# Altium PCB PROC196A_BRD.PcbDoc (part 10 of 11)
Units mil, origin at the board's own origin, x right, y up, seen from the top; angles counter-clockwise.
Board outline 3346.45 x 4921.26 mil, 8 copper layers (Top Layer, GND1, SIG1, PWR1, PWR2, SIG2, GND2, Bottom Layer), stack 54.534 mil thick; 736 components, 498 nets, 3030 pads, 1279 vias.
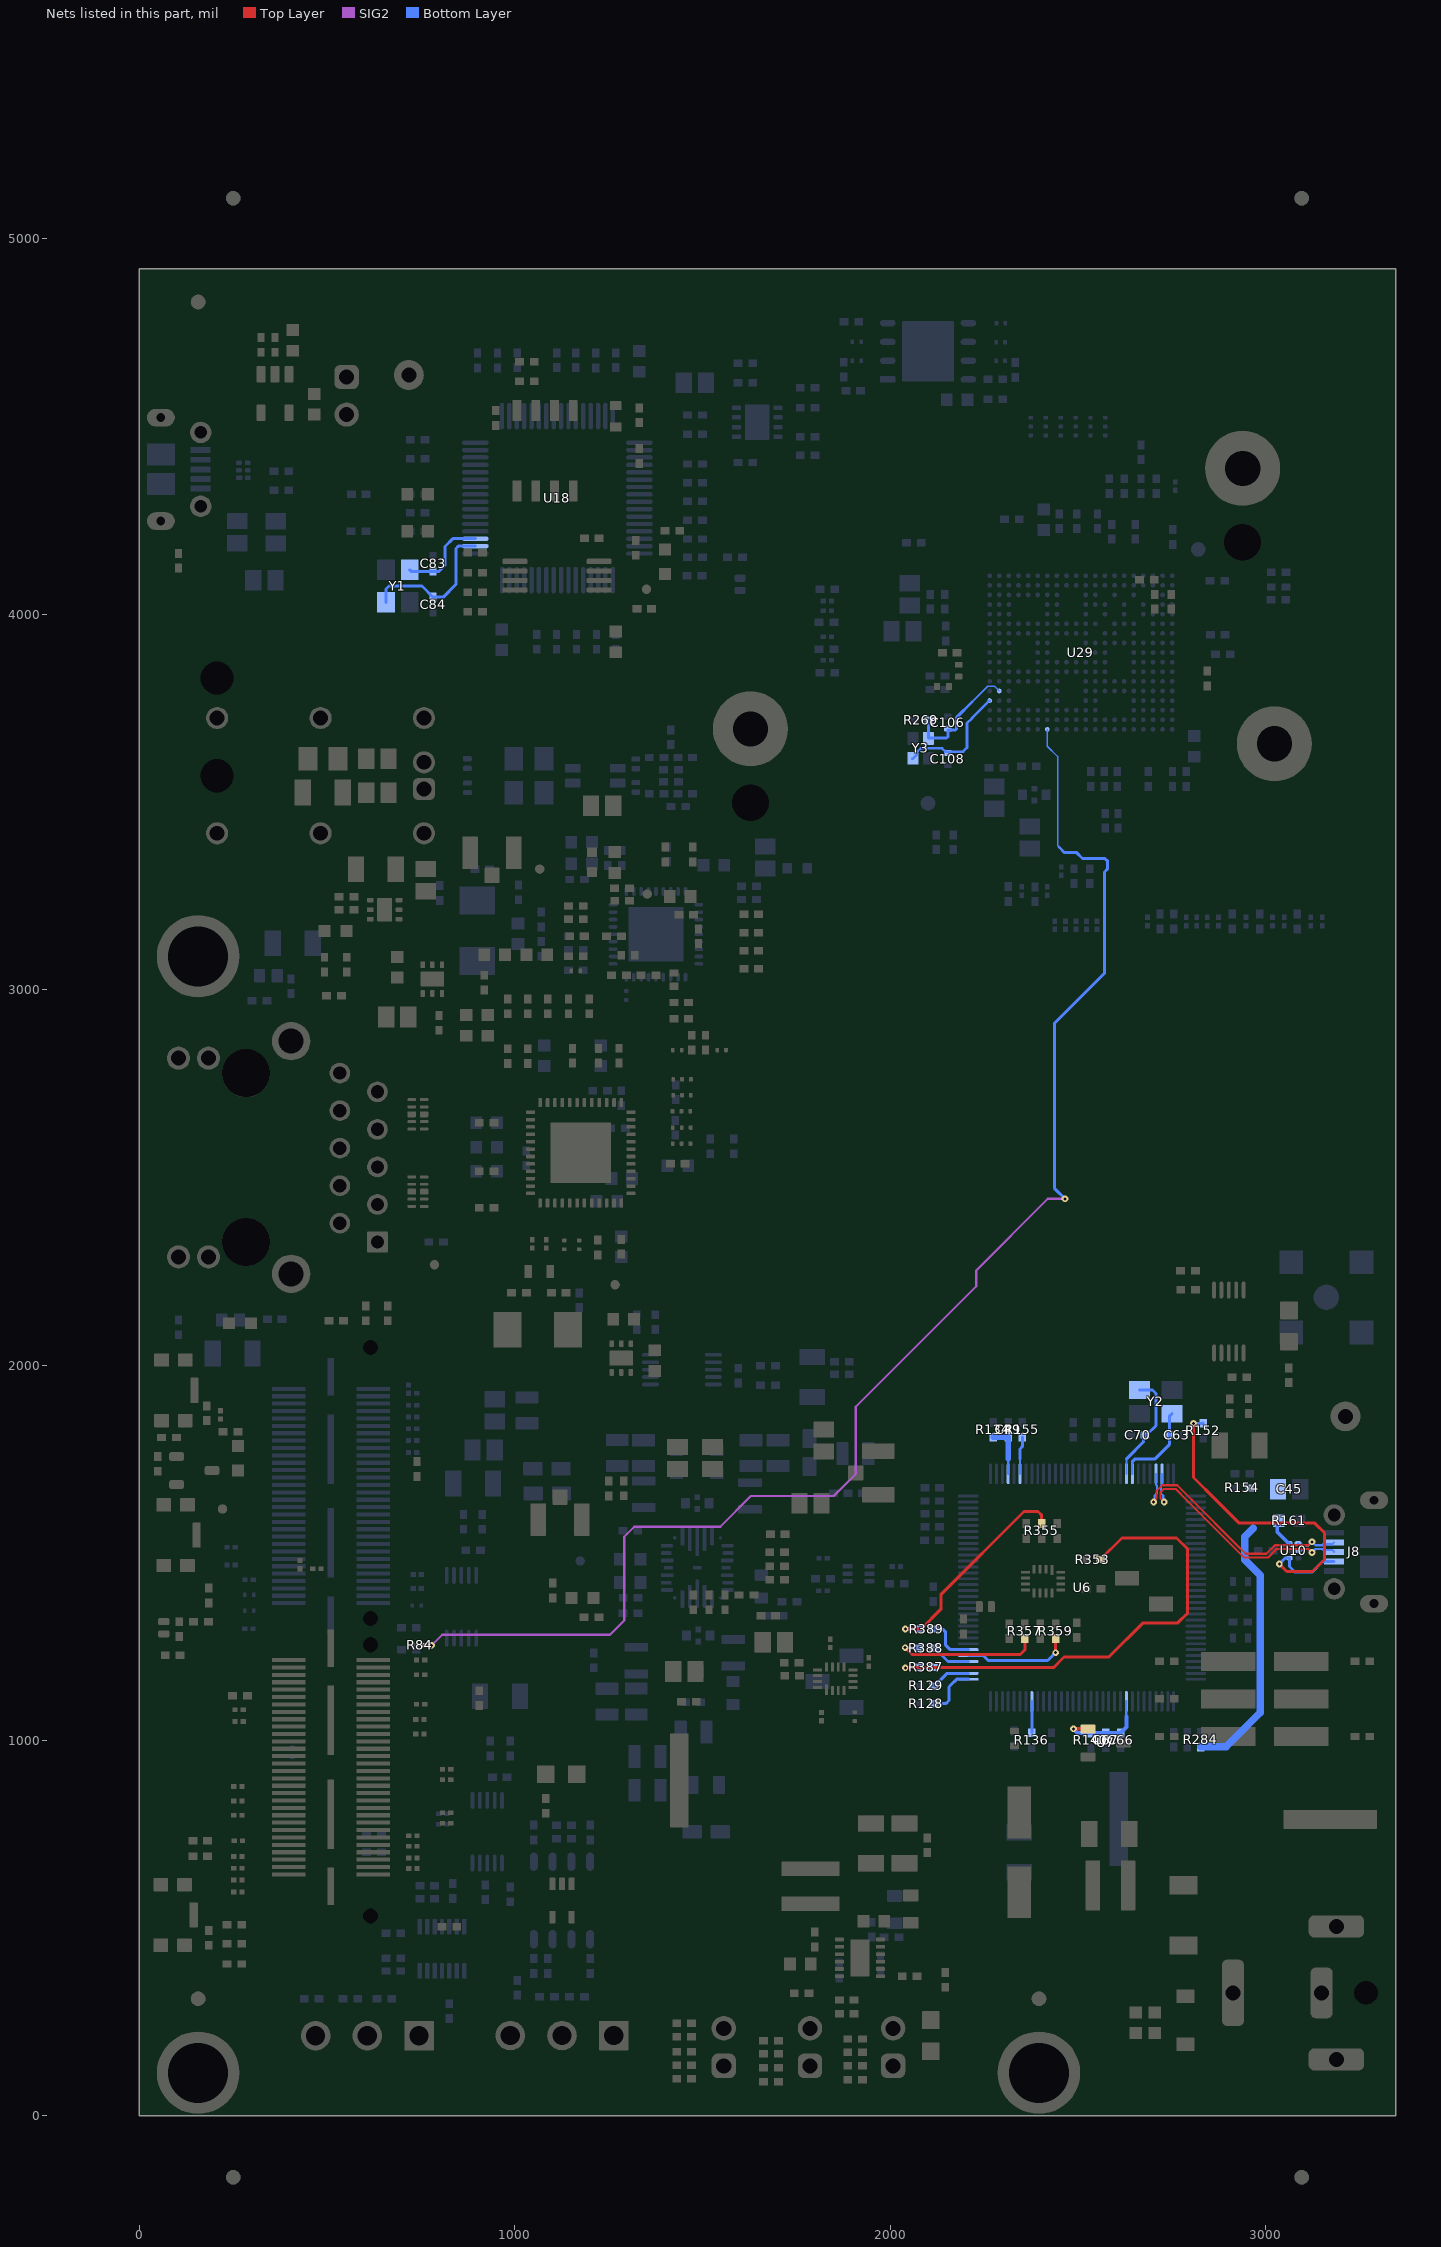
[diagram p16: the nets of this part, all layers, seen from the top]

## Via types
v1: diameter 18, hole 8, Top Layer to Bottom Layer, tented both sides, 1230 vias
v2: diameter 19.68, hole 7.87, Top Layer to Bottom Layer, 30 vias
v3: diameter 20, hole 10, Top Layer to Bottom Layer, tented both sides, 11 vias
v4: diameter 10, hole 4, SIG2 to Bottom Layer, tented both sides, 6 vias
v5: diameter 19.68, hole 7.87, Top Layer to Bottom Layer, tented both sides, 2 vias

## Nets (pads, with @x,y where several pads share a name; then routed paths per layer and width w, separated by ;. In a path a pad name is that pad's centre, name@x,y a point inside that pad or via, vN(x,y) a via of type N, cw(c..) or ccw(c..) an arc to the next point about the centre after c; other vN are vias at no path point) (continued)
XDS_TCK: R353.1 R387.1 | length 1284
  Top Layer w8: v1(2040.57,1193.5) 2040.92,1193.85 2435.24,1193.85 2463.4,1222.02 2582.67,1222.02 2674.07,1313.41 2766.68,1313.41 2792.65,1339.39 2792.65,1509.88 2763.28,1539.25 2617.53,1539.25 R353.1@2560.2,1481.93
  Bottom Layer w8: v1(2040.57,1193.5) 2041.1,1194.03 2072.24,1194.03 R387.1@2072.77,1194.56
XDS_TDI: R355.1 R389.1 | length 575.1
  Top Layer w8: v1(2040.67,1296.89) 2082.72,1296.89 2135.25,1349.42 2135.25,1388.25 2356.85,1609.86 2393.85,1609.86 2403.67,1600.04 R355.1@2403.67,1577.67
  Bottom Layer w8: v1(2040.67,1296.89) R389.1@2073.94,1296.89
XDS_TDO: R359.1 U6.37 | length 284.8
  Top Layer w8: R359.1@2440.88,1271.26 2441.05,1271.09 2441.05,1233.88 v1(2441.23,1233.71)
  Bottom Layer w8: U6.37@2208.34,1226.06 2247.87,1226.06 2261.17,1212.76 2419.8,1212.76 2440.75,1233.71 v1(2441.23,1233.71)
XDS_TMS: R357.1 R388.1 | length 395.1
  Top Layer w8: v1(2040.16,1247.13) 2058.47,1228.81 2346.5,1228.81 2358.88,1241.19 R357.1@2358.88,1271.26
  Bottom Layer w8: v1(2040.16,1247.13) 2040.66,1246.63 2072.85,1246.63 R388.1@2073.35,1246.13
XDSET_1_D_N: J8.2 U6.93 U10.1 | length 730.3
  Top Layer w5.65: v1(2702.21,1635.51) 2702.21,1637.21 2709.99,1644.99 2709.99,1665.1 2724.85,1679.96 2764.89,1679.96 2805.04,1639.81 2925.31,1519.53 2947.49,1497.36 3002.55,1497.36 3025.32,1520.13 3114.46,1520.13 3123.36,1529.03 v1(3123.95,1529.03)
  Bottom Layer w5.65: v1(2702.21,1635.51) 2704.57,1637.87 2704.57,1652.27 2711.11,1658.81 2711.11,1678.78 2708.76,1681.13 2708.76,1709.88 U6.93@2708.34,1710.31 ; U10.1@3086.64,1524.87 3089.03,1522.49 3097.09,1522.49 3099.46,1520.13 3114.46,1520.13 3123.36,1529.03 v1(3123.95,1529.03) 3124.53,1529.03 3133.43,1520.13 3151.2,1520.13 3153.85,1522.77 3178.02,1522.77 J8.2@3183.06,1527.82
XDSET_1_D_P: J8.3 U6.94 U10.2 | length 713.3
  Top Layer w5.65: v1(2730.21,1635.51) 2720.19,1645.53 2720.19,1660.87 2729.07,1669.76 2760.66,1669.76 2790.61,1639.81 2925.31,1505.11 2943.26,1487.16 3006.78,1487.16 3029.55,1509.93 3114.46,1509.93 3123.36,1501.03 v1(3123.95,1501.03)
  Bottom Layer w5.65: U6.94@2724.08,1710.31 2723.66,1709.88 2723.66,1681.13 2721.31,1678.78 2721.31,1658.81 2727.85,1652.27 2727.85,1637.87 v1(2730.21,1635.51) ; U10.2@3087.63,1505.18 3090.01,1507.56 3097.09,1507.56 3099.46,1509.93 3114.46,1509.93 3123.36,1501.03 v1(3123.95,1501.03) 3124.53,1501.03 3133.43,1509.93 3151.2,1509.93 3153.85,1507.28 3178.02,1507.28 J8.3@3183.06,1502.23
XDSET_1_ID: J8.4 R152.1 U10.4 | length 985.3
  Top Layer w8: v1(2808.45,1844.58) 2808.45,1700.36 2869,1639.81 2930,1578.81 3131.54,1578.81 3157.22,1553.13 3157.22,1481.93 3125.4,1450.11 3057.05,1450.11 v1(3036.9,1470.26)
  Bottom Layer w8: v1(2808.45,1844.58) 2808.73,1844.86 2833.61,1844.86 R152.1@2833.89,1845.13 ; v1(3036.9,1470.26) 3052.13,1485.5 U10.4@3064.01,1485.5 3064.01,1463.14 3078.75,1448.4 3123.69,1448.4 3151.93,1476.64 J8.4@3183.06,1476.64
XDSET_1_VBUS: C45.1 R154.2 R161.2 R284.2 U10.6 | length 788.4
  Bottom Layer w10: R161.2@3031.43,1585.36 3031.43,1555.48 3062.04,1524.87 U10.6@3064.01,1524.87
  Bottom Layer w20: R284.2@2828,982.63 2894.91,982.63 2986.69,1074.41 2986.69,1440.36 2945.42,1481.63 2945.42,1542.86 2967.36,1564.8
XDSET_NRST: R155.1 U6.70 | length 100
  Bottom Layer w6: U6.70@2346.13,1710.31 2346.13,1750.08
  Bottom Layer w8: 2346.13,1750.08 2346.27,1750.22 2346.27,1776.47 2352.4,1782.6 R155.1@2352.4,1807.73
XDSET_OSC0: C70.1 U6.88 Y2.1 | length 293.1
  Bottom Layer w6: U6.88@2629.6,1710.31 2629.6,1750.31
  Bottom Layer w8: 2629.6,1750.31 2629.95,1750.66 ; 2630.3,1750.31 2630.3,1750.8 2675.7,1796.2 2675.7,1810 C70.1@2679.33,1813.63 ; Y2.1@2664.34,1933.67 2699.14,1933.67 2708.25,1924.56 2708.25,1838.61 C70.1@2683.27,1813.63
XDSET_OSC1: C63.2 U6.89 Y2.3 | length 235.2
  Bottom Layer w6: U6.89@2645.34,1710.31 2645.34,1742.37
  Bottom Layer w8: 2645.34,1742.37 2653.07,1750.1 2706.08,1750.1 2743.77,1787.79 C63.2@2743.77,1813.63 2743.77,1863.49 Y2.3@2750.96,1870.68
XDSET_TCK: R387.2 U6.35 | length 92.3
  Bottom Layer w8: R387.2@2116.08,1194.56 U6.35@2208.34,1194.56
XDSET_TDI: R389.2 U6.38 | length 134.2
  Bottom Layer w7.8: 2180.78,1241.8 U6.38@2208.34,1241.8
  Bottom Layer w8: R389.2@2117.24,1296.89 2140.06,1296.89 2147.12,1289.83 2147.12,1255.17 2160.48,1241.8 2180.78,1241.8
XDSET_TMS: R388.2 U6.36 | length 101.8
  Bottom Layer w8: R388.2@2120.59,1244.16 2154.42,1210.32 U6.36@2208.34,1210.31
XDSET_UARTA_RX: R129.2 U6.34 | length 106.2
  Bottom Layer w8: R129.2@2116.08,1145.19 2118.05,1145.19 2145.52,1172.65 2151.67,1178.81 U6.34@2208.34,1178.81
XDSET_UARTA_TX: R128.2 U6.33 | length 139.8
  Bottom Layer w8: R128.2@2116.65,1097.79 2147.98,1097.79 2156.86,1106.67 2156.86,1142.59 2160.54,1146.27 2177.29,1163.03 U6.33@2184.66,1163.03 ; U6.33@2184.69,1163.06 U6.33@2208.34,1163.06
XDSET_UARTB_TX: R136.2 U6.25 | length 83.4
  Bottom Layer w8: R136.2@2377.63,1020.63 2377.63,1065.5 U6.25@2377.63,1104.01
XDSET_VBAT: C49.1 R134.1 U6.68 | length 136.9
  Bottom Layer w7: U6.68@2314.69,1710.36 2314.69,1748.26
  Bottom Layer w10: 2314.69,1748.26 2314.69,1750.65
  Bottom Layer w15: R134.1@2275.06,1807.73 C49.1@2314.64,1807.73 ; 2314.69,1750.65 C49.1@2314.69,1807.67
XDSET_VREFA: C66.2 C67.2 R140.1 U6.9 U7.1 | length 259.7
  Top Layer w10: v1(2488.42,1030.91) U7.1@2527.23,1030.91
  Bottom Layer w7: U6.9@2629.6,1104.01 2629.6,1064.04 2629.77,1063.86
  Bottom Layer w10: v1(2488.42,1030.91) 2499.28,1020.05 R140.1@2535.11,1020.05 C67.2@2574.86,1020.05 C66.2@2614.2,1020.05 2629.6,1035.45 2629.6,1064.04
XI_FTDI: C84.1 U18.2 Y1.1 | length 401.2
  Bottom Layer w8: Y1.1@657.29,4032.13 657.29,4067.56 665.17,4075.43 752.83,4075.43 C84.1@782.36,4045.91 809.61,4045.91 843.6,4079.89 843.6,4175.65 849.68,4181.73 U18.2@895.17,4181.73
XO_FTDI: C83.1 U18.3 Y1.3 | length 241.6
  Bottom Layer w8: Y1.3@720.28,4118.74 724.22,4114.8 C83.1@782.36,4114.8 798.14,4114.8 814.14,4130.81 814.14,4180.68 834.89,4201.42 U18.3@895.17,4201.42
XREF_CLK0: R84.1 U29.A7 | length 3902.6
  Top Layer w8: R84.1@758.27,1253.41 758.33,1253.36 778.61,1253.36 v1(778.66,1253.31)
  SIG2 w6: v1(778.66,1253.31) 807.16,1281.81 1253.81,1281.81 1291.44,1319.44 1291.44,1542.44 1318.5,1569.5 1547.5,1569.5 1629,1651 1849.99,1651 1908.75,1709.76 1908.75,1889.29 2229.37,2209.91 2229.37,2252.24 2420.08,2442.95 v1(2465.85,2442.95)
  Bottom Layer w4: U29.A7@2418.84,3693.52 2418.84,3648.89 2446.29,3621.44 2446.29,3383.85 2449.71,3380.43
  Bottom Layer w8: 2449.71,3380.43 2464.91,3365.24 2497.37,3365.24 2512.83,3349.78 2572.18,3349.78 2579.52,3342.44 2579.52,3322.46 2570.9,3313.84 2570.9,3043.71 2437.36,2910.17 2437.36,2471.44 v1(2465.85,2442.95)
XTALM: C108.1 U29.D1 Y3.3 | length 318.8
  Bottom Layer w7: Y3.3@2059.55,3615.18 2071.4,3627.03 2071.4,3632.67 2081.73,3643 2138.68,3643 2147.48,3634.2 2153.94,3634.2 2153.98,3634.16 2194.35,3634.16 2205,3644.81 2205,3709.99 2217.96,3722.95 2218.62,3723.61 U29.D1@2265.3,3770.29
XTALP: C106.1 R269.1 U29.E2 Y3.1 | length 325
  Bottom Layer w4: 2217.96,3766.53 2218.62,3767.19 2260.04,3808.61 2278.17,3808.61 U29.E2@2290.89,3795.89
  Bottom Layer w8: R269.1@2102.86,3718.43 2102.86,3670.3 2150.47,3670.3 2153.98,3673.82 C106.1@2153.98,3689.93 ; C106.1@2153.98,3692.03 2173.72,3692.03 2177.23,3695.54 2177.23,3725.81 2217.96,3766.53
pads on no net: D15.1S D15.2S D17.1S D17.2S D18.1S D18.2S D19.1S D19.2S FID1.1 FID2.1 FID3.1 FID4.1 FID5.1 FID6.1 FID7.1 FID8.1 FID9.1 FID10.1 FID11.1 FID12.1 FID13.1 FID14.1 FID15.1 FID16.1 J4.ALIGN1 J4.ALIGN2 J7.1 J7.2 J7.3 J7.14 J7.25 J7.31 J7.33 J7.35 J7.47 J7.MH1 J7.MH2 J8.7 J8.8 J9. J12.ALIGN J16.4 J19.10 J19.11 J19.14 J19.18 J19.20 J19.22 J19.24 J19.26 J19.28 J19.30 J19.32 J19.34 J19.35 J19.36 J19.37 J19.38 J19.39 J19.40 J19.41 J19.43 J19.45 J19.47 J19.49 J19.51 J19.53 J19.55 J19.59 J19.MH1 J19.MH2 LBL1.0 SW1.1 SW1.3 SW2.1 SW2.3 SW3.1 SW3.3 U2.11 U4.17 U4.18 U4.19 U4.20 U5.11 U6.2 U6.3 U6.4 U6.5 U6.6 U6.11 U6.12 U6.13 U6.14 U6.15 U6.18 U6.19 U6.20 U6.21 U6.22 U6.23 U6.24 U6.27 U6.29 U6.30 U6.31 U6.32 U6.41 U6.42 U6.43 U6.44 U6.45 U6.46 U6.49 U6.50 U6.53 U6.54 U6.56 U6.57 U6.65 U6.67 U6.71 U6.72 U6.73 U6.74 U6.75 U6.76 U6.77 U6.78 U6.81 U6.82 U6.83 U6.84 U6.85 U6.86 U6.91 U6.92 U6.97 U6.98 U6.99 U6.100 U6.102 U6.103 U6.104 U6.105 U6.106 U6.107 U6.108 U6.109 U6.110 U6.111 U6.112 U6.116 U6.117 U6.118 U6.119 U6.120 U6.121 U6.123 U6.124 U6.125 U6.126 U6.127 U6.128 U7.3 U9.3 U11.3 U12.3 U13.3@725.63,2668.11 U13.8@758.51,2668.11 U14.3@725.63,2462.03 U14.8@758.51,2462.03 U15.13 U15.20 U15.21 U15.22 U15.23 U15.48 U15.49@1121.99,2511.6 U15.49@1121.99,2565.54 U15.49@1121.99,2619.48 U15.49@1175.93,2511.6 U15.49@1175.93,2565.54 U15.49@1175.93,2619.48 U15.49@1229.86,2511.6 U15.49@1229.86,2565.54 U15.49@1229.86,2619.48 U16.5 U16.7@762.86,3028.35 U16.7@798.3,3028.35 U17.2 U17.5 U17.7@1266.22,2018.66 U17.7@1301.66,2018.66 U18.21 U18.22 U18.23 U18.24 U18.29 U18.30 U18.33 U18.40 U18.41 U18.43 U18.44 U18.57 U18.58 U18.59 U18.60 U19.6 U19.7 U20.7 U20.9@1645.89,4487 U20.9@1645.89,4536.61 U22.3 U27.4 U32.1 U33.7@653.41,3195.51 U33.7@653.41,3230.94

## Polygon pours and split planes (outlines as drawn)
GND on Top Layer "Top Layer-GND" (solid, remove dead copper, pour order 491): 3345.95,4921.06 3345.96,2921.78 3345.96,-0.19 -0.49,-0.19 -0.49,4921.06
3V3 on Top Layer "Top Layer-3V3" (solid, remove dead copper, pour order 306): 2899.79,1841.57 2899.79,1754.44 2912.56,1741.67 2912.56,1713.58 2817.58,1713.58 2817.58,1841.57
PMICOUT_1V8 on Top Layer "Top Layer-PMICOUT_1V8" (solid, remove dead copper, pour order 91): 1734.93,1993.84 1396.11,1993.84 1389.74,2000.93 1302.53,2000.93 1302.53,1935.81 1678.36,1935.81 1716.32,1897.86 1716.32,1821.54 1683.64,1788.86 1683.8,1674.22 1776.66,1674.22 1776.66,1952.1
1V2 on Top Layer "NONET_L-01_P-001" (solid, remove dead copper, pour order 12): 2672,4118 2676,4114 2676,4078.63 2673.4,4076.03 2659.03,4076.03 2648.69,4065.69 2648.69,4040.72 2669.61,4019.81 2763.09,4019.81 2763.09,3978 2618.85,3978 2607.15,3989.7 2607.6,3992 2607.6,4111.4 2607,4112 2613,4118
ERTH_GND on Top Layer "ERTH_GND_L01_P155" (solid, remove dead copper, pour order 155): 362.83,2133.63 482.54,2253.34 482.54,2818.61 523.85,2859.92 523.85,3099.48 374.2,3099.48 181.29,2906.57 0,2906.57 0,2214.38 144.93,2214.38 225.68,2133.63
3V3_VIO on Top Layer "Top Layer-3V3_VIO 1" (solid, pour order 15): 1657.48,1374.02 1622.05,1374.02 1622.05,1401.57 1688.98,1401.57 1712.6,1377.95 1712.6,1358.27 1755.91,1358.27 1771.65,1342.52 1771.65,1322.83 1755.91,1307.09 1681.1,1307.09 1681.1,1366.14 1677.17,1370.08
REGOUT_3V3 on Top Layer "Top Layer-REGOUT_3V3 5" (solid, pour order 35): 1589.76,1358.43 1605.03,1373.69 1618.17,1370.02 1649.61,1346.46 1669.29,1346.46 1669.29,1318.9 1589.76,1318.9
1V8_FILTERED on Top Layer "Top Layer-1V8_FILTERED" (solid, pour order 109): 1791.22,1791.63 1876.56,1791.63 1879.17,1790.09 1944.37,1724.88 1944.37,1698.73 1838.45,1592.81 1803.49,1592.81 1796.4,1599.91 1796.4,1680.45 1791.22,1685.62
AGND on Top Layer "AGND_L01_P083" (solid, pour order 83): 1547.63,1463.97 1519.54,1491.88 1503.96,1491.88 1494.48,1481.94 1477.42,1481.94 1470.52,1491.88 1453.33,1491.88 1422.63,1463.97 1422.63,1454.09 1451.77,1424.94 1464.92,1424.94 1476.93,1436.94 1493.43,1436.94 1505.42,1424.94 1519.13,1424.95 1547.63,1453.45
V3V3_PHY on Top Layer "Top Layer-V3V3_PHY" (solid, remove dead copper, pour order 473): 680.83,3248.56 693.5,3248.56 730.43,3285.5 812.08,3285.5 812.07,3189.54 741.36,3189.54 703.9,3227 680.83,3227
VBAT_INT on Top Layer "Top Layer-VBAT_INT 1" (solid, remove dead copper, pour order 461): 621.92,3230.25 621.92,3392.27 521.58,3392.27 521.58,3270.42 595.63,3270.42 595.63,3230.94
1V0_ETH2 on Top Layer "Top Layer-1V0_ETH2" (solid, pour order 444): 1533.35,3267.26 1454.57,3267.26 1452.34,3265.03 1452.34,3231.56 1464.84,3219.06 1464.84,3142.55 1533.35,3142.55
1V0_ETH2 on Top Layer "Top Layer-1V0_ETH2 1" (solid, pour order 438): 1210.04,3229.6 1210.04,3261.72 1193.24,3278.06 1193.24,3331.1 1284.77,3331.1 1284.77,3212.8 1226.84,3212.8
PVIN3V3 on Top Layer "Top Layer-REGOUT_3V3 2" (solid, pour order 434): 1451.41,1235.23 1451.41,1056 1374.21,1056 1374.21,1235.23
5V0 on Top Layer "Bottom Layer-5V0" (solid, remove dead copper, pour order 420): 1636.71,1296.64 1686.46,1296.9 1686.46,1210.31 1636.71,1210.31
VDDIO_ETH2 on Top Layer "Top Layer-VDDIO_ETH2" (solid, pour order 406): 955.19,3117.63 1053.4,3117.63 1053.4,3031.08 1053.81,3030.67 955.19,3030.67
REGOUT_3V3 on Top Layer "Top Layer-REGOUT_3V3 1" (solid, remove dead copper, pour order 404): 764.83,3172.17 634.18,3172.17 634.18,3060.82 743.4,3060.82 747.04,3057.18 764.83,3057.18
GND on Top Layer "Top Layer-GND 11" (solid, remove dead copper, pour order 402): 1531.07,983.22 1531.07,741.65 1506.21,716.79 1416.2,716.79 1406.4,726.59 1406.4,1023.56 1408.85,1026.01 1510.05,1026.01 1530.2,1005.87
NetJ10_6 on Top Layer "Top Layer-NetJ10_6" (solid, remove dead copper, pour order 362): 192.3,4450.41 199.96,4458.07 199.96,4517.55 164.33,4553.18 -19.57,4553.18 -19.57,4151.18 192.3,4151.18 192.3,4304.73 179.15,4317.88 113.86,4317.88 104.25,4327.49 104.25,4449.7
1V0_ETH on Top Layer "Top Layer-1V0_ETH" (solid, remove dead copper, pour order 348): 1296.98,2141.21 1311.38,2155.61 1386.85,2155.61 1395.36,2164.13 1395.36,2183.88 1459.39,2183.88 1459.39,2075.16 1356.85,2075.16 1329.08,2047.39 1302.53,2047.39 1302.53,2092.99 1296.98,2098.54
GND on Top Layer "Top Layer-GND 2" (solid, remove dead copper, pour order 346): 2176.78,711.94 2577.25,711.94 2577.25,932.74 2176.78,932.74
NetC149_2 on Top Layer "Top Layer-NetC144_1" (solid, remove dead copper, pour order 320): 513.96,4556.1 528.55,4570.69 590.17,4570.69 590.17,4506.02 560.91,4476.76 373.17,4476.76 373.17,4556.1
GND on Top Layer "Top Layer-GND 4" (solid, remove dead copper, pour order 312): 2528.58,0 2528.58,233.08 2804.91,233.08 2847.83,190.17 3057.35,190.17 3057.35,834.26 3346.48,834.26 3346.48,0
2V5_ETH on Top Layer "Top Layer-2V5_ETH" (solid, remove dead copper, pour order 310): 763.1,2998.19 763.1,2863.36 693.44,2863.36 693.44,2953.71 737.93,2998.19
PVIN3V3 on Top Layer "Top Layer-REGOUT_3V3 3" (solid, remove dead copper, pour order 191): 1559.41,1645.77 1573.41,1659.77 1573.59,1745.55 1395.36,1745.55 1395.36,1634.29 1406.47,1623.18 1445.2,1623.18 1467.8,1645.77
3V3_VIO on Top Layer "Top Layer-REGOUT_3V3 4" (solid, remove dead copper, pour order 296): 2961.69,1832.51 2961.69,1714.16 3052.13,1714.16 3052.13,1832.51
VDDIO_ETH on Top Layer "Top Layer-VDDIO_ETH" (solid, remove dead copper, pour order 271): 1210.1,3009.46 1210.1,2965.79 905.21,2965.79 905.21,3009.46
GND on Top Layer "Top Layer-GND 1" (solid, remove dead copper, pour order 263): 1884.61,296.8 1884.61,710.97 2144.31,710.97 2144.31,567.75 1943.12,567.75 1943.12,296.8
NetC21_2 on Top Layer "Top Layer-NetC21_2" (solid, remove dead copper, pour order 259): 1878.5,463.27 1878.5,592.57 1686.46,592.57 1686.46,470.73 1828.07,470.73 1828.07,463.27
REGOUT_3V3 on Top Layer "Top Layer-REGOUT_3V3" (solid, remove dead copper, pour order 211): 2109.97,923.35 2121.65,911.99 2121.65,732.61 1872.59,732.61 1872.59,620.13 1691.73,620.13 1691.73,815.1 1799.98,923.35
VBAT_INT on Top Layer "Top Layer-VBAT_INT" (solid, remove dead copper, pour order 203): 2577.25,377.21 2076.18,377.2 1993.39,460 1962.34,460 1962.34,542.58 2187.62,542.58 2187.62,699.15 2577.25,699.15
NetC100_1 on Top Layer "Top Layer-NetC100_1" (solid, remove dead copper, pour order 199): 2906.52,534.03 2906.52,816.38 2870.34,852.57 2626.94,852.57 2598.1,823.73 2598.1,534.03
NetC104_1 on Top Layer "Top Layer-NetC104_1" (solid, remove dead copper, pour order 193): 2640.27,505.4 2904.71,505.4 2947.34,462.78 2947.34,239.11 2841.68,239.11 2828.7,252.09 2624.02,252.09 2599.66,276.45 2599.66,464.79
GND on GND2 "GND1-GND" (solid, remove dead copper, pour order 449): 0,4921.25 3346.45,4921.25 3346.45,0 0,0
ERTH_GND on GND2 "ERTH_GND_L07_P410" (solid, remove dead copper, pour order 410): 362.83,2133.24 482.54,2252.95 482.54,2818.22 523.85,2859.53 523.85,3099.09 374.2,3099.09 181.29,2906.18 0,2906.18 0,2213.99 144.93,2213.99 225.68,2133.24
AGND on GND2 "AGND_L07_P289" (solid, pour order 289): 1547.63,1463.97 1519.54,1491.88 1503.96,1491.88 1494.48,1481.94 1477.42,1481.94 1470.52,1491.88 1453.33,1491.88 1422.63,1463.97 1422.63,1454.09 1451.77,1424.94 1464.92,1424.94 1476.93,1436.94 1493.43,1436.94 1505.42,1424.94 1519.13,1424.95 1547.63,1453.45
GND on GND1 "" (solid, remove dead copper, pour order 451): 0,4921.26 3346.45,4921.26 3346.45,0 0,0
ERTH_GND on GND1 "ERTH_GND_L02_P416" (solid, remove dead copper, pour order 416): 362.83,2133.63 482.54,2253.34 482.54,2818.61 523.85,2859.92 523.85,3099.48 374.2,3099.48 181.29,2906.57 0,2906.57 0,2214.38 144.93,2214.38 225.68,2133.63
AGND on GND1 "AGND_L02_P283" (solid, pour order 283): 1547.63,1463.97 1519.54,1491.88 1503.96,1491.88 1494.48,1481.94 1477.42,1481.94 1470.52,1491.88 1453.33,1491.88 1422.63,1463.97 1422.63,1454.09 1451.77,1424.94 1464.92,1424.94 1476.93,1436.94 1493.43,1436.94 1505.42,1424.94 1519.13,1424.95 1547.63,1453.45
GND on SIG1 "GND_L03_P459" (solid, remove dead copper, pour order 459): 0,4921.25 0,0 3346.45,0 3346.45,4921.25
FTDI_VBUS on SIG1 "SIG1-FTDI_VBUS" (solid, remove dead copper, pour order 336): 1554.4,4330.22 1623.26,4330.22 1623.26,4445.07 1555.33,4445.07
AGND on SIG1 "AGND_L03_P253" (solid, pour order 253): 1547.63,1463.97 1519.54,1491.88 1503.96,1491.88 1494.48,1481.94 1477.42,1481.94 1470.52,1491.88 1453.33,1491.88 1422.63,1463.97 1422.63,1454.09 1451.77,1424.94 1464.92,1424.94 1476.93,1436.94 1493.43,1436.94 1505.42,1424.94 1519.13,1424.95 1547.63,1453.45
FTDI_VBUS on SIG1 "SIG1-FTDI_VBUS 1" (solid, remove dead copper, pour order 255): 343.71,4161.9 343.71,4086.01 457.04,4086.01 457.04,4161.9
GND on Bottom Layer "Bottom Layer-GND 7" (solid, remove dead copper, pour order 492): 0,4921.26 3346.45,4921.26 3346.45,0.01 0,0.01
1V2 on Bottom Layer "NONET_L-01_P-001" (solid, remove dead copper, pour order 121): 2561.95,4051.79 2561.95,3977.86 2575.61,3964.2 2699.97,3964.2 2710.78,3975.02 2710.78,4033.15 2679.12,4064.81 2574.97,4064.81
GND on Bottom Layer "NONET_L-01_P-001" (solid, remove dead copper, pour order 493): 2118.44,3789.97 2078.84,3789.97 2071,3797.81 2071,3842.81 2074,3845.81 2118.22,3845.81 2118.44,3845.59
1V2 on Bottom Layer "NONET_L-01_P-001" (solid, remove dead copper, pour order 115): 2664,4169 2665,4168 2665,4126 2646.33,4126 2640.91,4131.42 2640.91,4212.13 2642.78,4214 2643.78,4213 2691.62,4212.27 2694.47,4212.27 2700,4206.74 2700,4190 2699,4189 2666,4189 2664,4187
1V8 on Bottom Layer "NONET_L-01_P-001" (solid, pour order 87): 2163,3784 2164,3783 2189,3783 2189,3816.63 2223,3850.63 2223,3908.21 2222.77,3908.44 2194.44,3908.44 2163,3877
1V2 on Bottom Layer "Bottom Layer-1V2" (solid, remove dead copper, pour order 440): 804.55,970.96 827.46,948.05 865.19,948.05 891.32,922.8 913.97,922.8 913.97,1021.74 931.35,1039.12 931.35,1157.27 804.55,1157.27
1V0 on Bottom Layer "NONET_L-01_P-001" (solid, remove dead copper, pour order 125): 2358.57,3695.44 2363.51,3700.38 2370.5,3700.38 2374.52,3696.36 2374.52,3634.48 2370.51,3630.47 2370.51,3590.24 2403.19,3590.24 2427.46,3565.96 2427.46,3411.81 2325,3411.81 2320,3416.81 2320,3461.81 2338.19,3480 2338.19,3635.47 2358.57,3655.85
1V8 on Bottom Layer "NONET_L-01_P-001" (solid, remove dead copper, pour order 133): 2349,3693.46 2348.93,3693.52 2348.93,3696.36 2344.91,3700.38 2339.23,3700.38 2335.21,3696.36 2335.21,3668.38 2291.47,3624.63 2291.47,3590.24 2270.39,3569.16 2234.35,3569.16 2229.72,3564.53 2229.72,3524.39 2235.61,3518.5 2315.09,3518.5 2315.09,3567.68 2315.09,3626.05 2344.07,3655.03 2349,3659.96
1V0 on Bottom Layer "NONET_L-01_P-001" (solid, remove dead copper, pour order 145): 2041,3917.6 2040,3916.6 2040,3884.81 2048,3884.81 2112,3884.81 2130.53,3903.34 2130.53,3949.08 2166.4,3949.08 2172.91,3942.57 2268.14,3942.57 2272.16,3946.59 2272.16,3952.27 2268.14,3956.29 2187.73,3956.29 2162.7,3981.32 2041,3981.32
XDSET_1_VBUS on Bottom Layer "Bottom Layer-XDSET_1_VBUS" (solid, remove dead copper, pour order 225): 3056.95,1709.2 3056.95,1541.6 2945.42,1541.6 2945.42,1709.2
1V2 on Bottom Layer "NONET_L-01_P-001" (solid, remove dead copper, pour order 149): 2448.54,4154.73 2439,4145.18 2439,4118.16 2444.43,4112.72 2445.71,4114 2453.04,4114 2457.54,4114 2473.89,4130.35 2473.89,4205.75 2469.96,4209.67 2471.11,4210.82 2471.11,4240.27 2396.46,4240.27 2391.97,4235.78 2391.97,4211.76 2394.73,4209 2435,4209 2448.54,4195.45
1V0_ETH on Bottom Layer "PWR2-1V0_ETH" (solid, pour order 446): 1393.69,2080.95 1393.69,2210.22 1034.65,2210.22 1034.65,2556.29 936.38,2556.29 936.38,2617.56 1034.65,2617.56 1034.65,2828.69 1175.77,2828.69 1175.77,2652.82 1375.14,2652.82 1375.14,2374.87 1555.93,2374.87 1555.93,2080.95
GND on Bottom Layer "NONET_L-01_P-001" (solid, remove dead copper, pour order 135): 2305.09,3503.94 2305.09,3441.02 2298,3433.93 2226.81,3433.93 2223.83,3436.91 2223.83,3501.92 2225.85,3503.94
1V8 on Bottom Layer "NONET_L-01_P-001" (solid, remove dead copper, pour order 147): 2158.36,4002.14 1994.67,4002.14 1980,4016.81 1980,4049.71 1987.1,4056.81 2016.08,4056.81 2027.44,4045.45 2069.61,4045.45 2089.3,4025.76 2158.36,4025.76
VDDIO_ETH on Bottom Layer "PWR1-VDDIO_ETH" (solid, remove dead copper, pour order 185): 984.96,3016.36 1217.2,3016.36 1450.74,2782.81 1450.74,2515.26 1380.61,2515.26 1380.6,2660.05 1252.98,2660.05 1252.98,2372.47 1208.98,2372.47 1158.74,2422.71 1158.74,2674.37 1181.38,2697.95 1181.38,2884.55 1131.07,2934.86 984.96,2934.86
PMICOUT_1V0 on Bottom Layer "Bottom Layer-PMICOUT_1V0" (solid, remove dead copper, pour order 177): 1166.09,1760.25 1095.11,1760.24 1095.11,1624.35 1238.8,1624.35 1290.02,1675.57 1383.44,1675.57 1383.44,1760.25
PMICOUT_1V8 on Bottom Layer "Bottom Layer-PMICOUT_1V8" (solid, remove dead copper, pour order 235): 1786.32,1684.43 1786.32,1695 1790.94,1699.62 1799.04,1699.68 1805.73,1706.38 1805.73,1759.4 1757.01,1759.4 1591.37,1759.4 1591.37,1657.99 1673.41,1657.99 1727.57,1603.83 1847.19,1603.83 1861.42,1618.06 1861.42,1667.05 1859.46,1669 1837.65,1669 1829.93,1661.29 1794.04,1661.29 1786.32,1669
1V8_FILTERED on Bottom Layer "Bottom Layer-1V8_FILTERED" (solid, pour order 167): 1749.4,1935.16 1749.4,1790.79 1759.55,1780.64 1818.4,1780.64 1832.34,1766.7 1832.34,1719.61 1806.11,1693.38 1799.01,1693.38 1793.06,1687.44 1793.06,1673.86 1799.01,1667.92 1823.55,1667.92 1831.5,1675.86 1894.04,1675.86 1907.78,1689.6 1907.78,1815.13 1865.47,1857.44 1865.47,1912.74 1840.65,1937.57 1810.3,1937.57
1V8 on Bottom Layer "Bottom Layer-1V8" (solid, remove dead copper, pour order 249): 1831.91,1992.61 1836.46,1997.16 1865.47,1997.16 1865.47,2098.04 1682.73,2098.04 1682.73,2041.08 1725.14,2041.08 1725.14,1992.61
PVIN3V3 on Bottom Layer "Bottom Layer-REGOUT_3V3 3" (solid, pour order 484): 1466.6,986.03 1496.16,956.47 1496.16,731.58 1360.65,731.58 1360.65,977.28 1377.81,994.44 1377.81,1228.58 1446.31,1297.08 1470.15,1297.28 1470.15,1260.28 1454.58,1244.71 1454.58,1142.28 1466.6,1130.26
REGOUT_3V3 on Bottom Layer "Bottom Layer-REGOUT_3V3 6" (solid, remove dead copper, pour order 187): 1522.48,733.15 1840.23,733.15 2121.65,733.15 2121.65,968.98 1522.48,968.98
3V3_VIO on Bottom Layer "Bottom Layer-3V3_VIO" (solid, pour order 153): 1702.71,1345.43 1774.98,1345.43 1774.98,1314.37 1702.71,1314.37
1V0_FILTERED on Bottom Layer "Bottom Layer-1V0_FILTERED" (solid, pour order 169): 918.87,1869.5 1075.07,1869.5 1075.07,1636.05 931.63,1636.05 918.87,1648.81 918.87,1747.25
AGND on Bottom Layer "AGND_L08_P165" (solid, pour order 165): 1547.63,1463.97 1519.54,1491.88 1503.96,1491.88 1494.48,1481.94 1477.42,1481.94 1470.52,1491.88 1453.33,1491.88 1422.63,1463.97 1422.63,1454.09 1451.77,1424.94 1464.92,1424.94 1476.93,1436.94 1493.43,1436.94 1505.42,1424.94 1519.13,1424.95 1547.63,1453.45
PVIN3V3 on Bottom Layer "Bottom Layer-REGOUT_3V3 1" (solid, pour order 487): 1466.76,1644.51 1460.8,1650.47 1460.75,1729.26 1402.02,1729.26 1402.02,1645.17 1458.23,1588.96 1458.23,1575.74 1458.23,1503.49 1472.92,1503.49 1472.92,1600.18 1466.76,1606.35
5V0 on Bottom Layer "Bottom Layer-5V0" (solid, remove dead copper, pour order 482): 1684.95,1295.89 1636.71,1296.13 1636.71,1209.59 1684.95,1209.59
PVIN3V3 on Bottom Layer "Bottom Layer-REGOUT_3V3" (solid, pour order 490): 1505.65,1646.73 1512.01,1653.08 1512.01,1730.3 1568.31,1730.3 1568.31,1644.17 1514.14,1590 1514.14,1504.53 1499.44,1504.53 1499.44,1601.22 1505.61,1607.38
PVIN3V3 on Bottom Layer "Bottom Layer-REGOUT_3V3 2" (solid, pour order 485): 1546.68,1151.82 1559.01,1139.49 1656.63,1139.49 1656.63,1181.54 1622.07,1216.11 1546.68,1216.11
NetC37_1 on Bottom Layer "Bottom Layer-NetC37_1" (solid, pour order 483): 1743.59,3352.16 1743.59,3293.7 1628.3,3293.7 1624.26,3289.66 1624.26,3219.14 1539.46,3219.14 1539.46,3352.16
NetL1_1 on Bottom Layer "Bottom Layer-NetL1_1" (solid, remove dead copper, pour order 481): 1546.48,1309.05 1609.1,1309.05 1617.33,1300.82 1617.33,1250.76 1546.48,1250.76
FTDI_VCORE on Bottom Layer "Bottom Layer-FTDI_VCORE" (solid, remove dead copper, pour order 480): 1336.52,4130.81 1336.52,3960.03 1308.62,3960.03 1282.85,3985.81 1282.85,4019.21 1253.89,4048.17 1253.89,4130.81
NetJ8_1 on Bottom Layer "Bottom Layer-NetJ8_1" (solid, remove dead copper, pour order 477): 3068.74,1560.77 3083.29,1546.22 3213.15,1546.22 3213.15,1564.8 3164.43,1564.8 3115.35,1613.88 3068.74,1613.88
NetJ10_6 on Bottom Layer "Bottom Layer-NetJ10_6" (solid, remove dead copper, pour order 469): 192.3,4450.41 199.96,4458.07 199.96,4517.55 164.33,4553.18 -19.57,4553.18 -19.57,4151.18 189.34,4151.18 189.34,4307.69 179.15,4317.88 113.86,4317.88 104.25,4327.49 104.25,4449.7
NetJ9_16 on Bottom Layer "Bottom Layer-NetJ9_16" (solid, remove dead copper, pour order 465): 459.43,2999.34 459.43,2839.67 427.54,2807.77 374.98,2807.77 349.71,2833.05 349.71,2902.87 379.45,2932.61 379.45,2999.34
ERTH_GND on Bottom Layer "Bottom Layer-ERTH_GND 1" (solid, remove dead copper, pour order 448): 354.63,3081.36 405.78,3081.36 423.43,3099.01 423.43,3164.17 495.63,3164.22 495.63,3016.36 354.63,3016.36
2V5_ETH on Bottom Layer "PWR2-2V5_ETH" (solid, pour order 189): 834.89,2681.38 931.63,2681.38 931.63,2628.93 1017.9,2628.93 1017.9,2688.6 801.1,2905.4 692.55,2905.4 692.55,2873.55 728.68,2837.42 728.68,2437.76 1005.4,2437.75 1005.4,2530.68 931.38,2530.68 931.38,2491.6 834.89,2491.6
GND on Bottom Layer "Bottom Layer-GND 9" (solid, remove dead copper, pour order 436): 1911.15,560.1 2159.56,560.1 2159.56,688.12 1911.15,688.12
GND on Bottom Layer "Bottom Layer-GND 10" (solid, remove dead copper, pour order 430): 2637.87,728.98 2637.87,661.46 2609.43,633.01 2546.62,633.01 2450.65,728.98 2158.49,728.98 2158.49,914.51 2640.12,914.51 2640.12,728.98
VBAT_INT on Bottom Layer "Bottom Layer-VBAT_INT 1" (solid, remove dead copper, pour order 412): 2201,396.79 2201,671.21 2472.12,671.21 2472.12,396.79
5V0 on Bottom Layer "Bottom Layer-5V0 1" (solid, remove dead copper, pour order 374): 759.65,655.44 759.65,598.77 702.41,598.77 702.41,655.44
5V0 on Bottom Layer "Bottom Layer-5V0 2" (solid, remove dead copper, pour order 97): 1131.24,760.44 1131.24,833 1071.17,833 1071.17,760.44
GND on Bottom Layer "Bottom Layer-GND 1" (solid, remove dead copper, pour order 372): 243.02,2148.54 243.02,2091.27 228.64,2076.9 228.64,1956.13 144.59,1956.13 144.59,2148.54
ERTH_GND on Bottom Layer "Bottom Layer-ERTH_GND" (solid, remove dead copper, pour order 370): 253.7,2228.6 351.78,2228.6 351.78,1975.88 252.91,1975.88
NetJ9_15 on Bottom Layer "Bottom Layer-NetJ9_15" (solid, remove dead copper, pour order 358): 366.88,2100.54 366.88,2202.15 351.78,2217.25 351.78,2275.46 382.29,2305.97 464.22,2305.97 464.22,2100.54
SW_B3 on Bottom Layer "Bottom Layer-SW1" (solid, remove dead copper, pour order 342): 1282.35,1277.84 1358.03,1277.84 1435.17,1354.98 1435.17,1371.62 1437.71,1374.16 1449.96,1374.16 1449.96,1323.14 1359.17,1232.35 1282.35,1232.35
FTDI_VBUS on Bottom Layer "Bottom Layer-FTDI_VBUS" (solid, remove dead copper, pour order 324): 1551.43,4505.43 1551.43,4332.46 1608.28,4332.46 1608.28,4504.67 1607.52,4505.43
VLDO_3V3 on Bottom Layer "Bottom Layer-VLDO_3V3" (solid, remove dead copper, pour order 318): 1550.02,4540.03 1530.63,4559.41 1491.9,4559.33 1492.23,4690.51 1614.4,4690.51 1614.4,4595.35 1600.64,4581.59 1600.64,4520.61 1550.02,4520.61
FTDI_3V3 on Bottom Layer "Bottom Layer-FTDI_3V3" (solid, remove dead copper, pour order 279): 1247.52,4672.69 1468.62,4672.69 1468.62,4570.69 1325.51,4570.69 1313.48,4582.73 1272.92,4582.73 1247.36,4608.28
FTDI_3V3 on Bottom Layer "Bottom Layer-FTDI_3V3 1" (solid, remove dead copper, pour order 277): 580.93,4199.45 580.93,4341.18 521.58,4341.18 521.58,4199.45
FTDI_VBUS on Bottom Layer "Bottom Layer-FTDI_VBUS 1" (solid, remove dead copper, pour order 275): 208.05,4209.29 295.09,4209.29 450.34,4209.29 450.34,4038.03 339.78,4038.03 339.78,4142.83 208.05,4142.83
NetC97_1 on Bottom Layer "Bottom Layer-NetC97_1" (solid, remove dead copper, pour order 273): 370.95,4224.79 405.68,4224.79 405.68,4281.04 370.96,4315.75 370.96,4352.47 352.96,4370.48 284.18,4370.48 284.18,4341.18 319.92,4305.43 319.92,4224.79
NetJ10_1 on Bottom Layer "Bottom Layer-NetJ10_1" (solid, remove dead copper, pour order 269): 133.34,4342.92 243.46,4342.92 295.09,4291.29 295.09,4229.02 208.81,4229.02 208.81,4288.22 179.15,4317.88 133.86,4317.88
SW_B2 on Bottom Layer "Bottom Layer-SW2" (solid, remove dead copper, pour order 267): 1359.49,1596.04 1314.84,1596.04 1305.59,1608.94 1305.59,1647.92 1375.99,1647.92 1452.94,1570.96 1452.94,1517.76 1439.67,1517.76 1439.67,1551.55 1439.67,1570.43 1430.26,1579.84 1375.69,1579.84
SW_B1 on Bottom Layer "Bottom Layer-SW3" (solid, remove dead copper, pour order 251): 1536.74,1570.3 1547.79,1570.3 1570.99,1593.5 1664.28,1593.5 1664.29,1637.29 1578.72,1637.29 1536.74,1595.9
1V0 on Bottom Layer "Bottom Layer-1V0_RF1" (solid, remove dead copper, pour order 231): 833.57,1626.99 833.57,1579.84 724.34,1579.84 724.34,1720.94 860.43,1720.94 860.43,1626.99
PMICOUT_1V2 on Bottom Layer "Bottom Layer-PMICOUT_1V2" (solid, remove dead copper, pour order 229): 1067.27,1033.74 1142.48,1108.95 1358.31,1108.95 1358.31,1205.58 990.56,1205.62 990.56,1033.74
VBAT_INT on Bottom Layer "Bottom Layer-VBAT_INT" (solid, remove dead copper, pour order 227): 1971.38,494.92 2009.68,494.92 2009.68,410.79 2155.08,410.79 2155.08,540.26 1971.38,540.26
GND on SIG2 "GND_L06_P452" (solid, remove dead copper, pour order 452): 0,4921.26 0,0.01 3346.45,0.01 3346.45,4921.26
AGND on SIG2 "AGND_L06_P304" (solid, pour order 304): 1547.63,1463.97 1519.54,1491.88 1503.96,1491.88 1494.48,1481.94 1477.42,1481.94 1470.52,1491.88 1453.33,1491.88 1422.63,1463.97 1422.63,1454.09 1451.77,1424.94 1464.92,1424.94 1476.93,1436.94 1493.43,1436.94 1505.42,1424.94 1519.13,1424.95 1547.63,1453.45
GND on PWR1 "GND1-GND" (solid, remove dead copper, pour order 495): 0,4933.06 3346.45,4933.06 3346.45,0 0,0
3V3_VIO on PWR1 "NONET_L-01_P-001" (solid, remove dead copper, pour order 388): 2794.37,3503.81 2791.82,3506.36 2791.82,3544.34 2891.48,3544.34 2906,3529.81 2882,3503.81
1V8 on PWR1 "NONET_L-01_P-001" (solid, remove dead copper, pour order 81): 2101.19,3994.81 2130,3966 2130,3592 2202.88,3519.12 2246.31,3519.12 2263,3535.81 2263,3570.81 2320,3627.81 2367.85,3627.81 2376.96,3636.93 2412.39,3636.93 2480.68,3568.64 2480.68,3506.13 2505,3481.81 2592.13,3481.81 2659.02,3414.92 2659.02,2867.08 1896.75,2104.81 1744,2104.81 1740,2100.81 1740,2050.81 1746,2044.81 2193.22,2044.81 2815,2666.59 2815,3369.23 2673,3511.23 2673,3535.81 2731.16,3593.97 2870.5,3593.97 3084.18,3807.65 3084.18,4254.63 3049,4289.81 2824.5,4289.81 2594,4289.81 2553,4248.81 2538,4248.81 2533,4243.81 2533,4199.81 2541,4191.81 2555.84,4191.81 2621,4191.81 2667.81,4145 2864.81,4145 2889.65,4120.16 2889.65,4027.14 2806,3943.49 2806,3848.62 2785.73,3828.35 2712.63,3828.35 2702.62,3818.34 2702.62,3808.36 2712.58,3798.09 2723.76,3786.9 2723.76,3749.2 2670.38,3695.81 2308,3695.81 2288.41,3696 2248,3736.41 2248,4024 2202.19,4069.81 1981,4069.81 1968,4056.81 1968,4015.81 1989,3994.81
5V0 on PWR1 "PWR1-5V0" (solid, remove dead copper, pour order 77): 1041.31,719 871.62,719 871.62,718.61 870.56,717 870.56,710.42 752.14,592.08 717.95,592.28 705.99,592.28 704.89,854.2 744.5,893.81 952.17,893.81 1167.17,1108.81 1481.86,1108.81 1606.05,1233 1707.91,1233 1733.54,1196.63 1733.54,876.81 1199.12,876.81
1V0 on PWR1 "PWR1-1V0_RF1" (solid, remove dead copper, pour order 384): 2080,3900 2067,3887 2067,3520 2114.19,3472.81 2161.5,3472.81 2275,3472.81 2319,3516.81 2319,3553.81 2342.75,3577.56 2365.27,3577.56 2373.09,3569.54 2373.09,3537.72 2381,3529.81 2398,3529.81 2429,3498.81 2429,3418.43 2413.38,3402.81 2276,3402.81 2191,3317.81 2191,3052.81 2001.84,2863.65 1456.92,2863.65 1400.81,2807.54 1400.81,2619.43 1363.02,2581.64 1363.02,2494.21 1291.95,2423.14 1204.52,2423.14 1087.72,2306.34 1087.72,2219.98 1128,2179.7 1128,1579.74 877.03,1579.74 727.08,1579.74 727.08,1582 727.08,1656.62 724.7,1659 742.7,1677 746.39,1677 773.93,1677 897.44,1800.51 897.44,1937.01 897.44,2293.05 897.44,2532.75 1085.58,2720.9 1137.95,2720.23 1209.47,2791.75 1209.47,2844.79 1490.04,3125.35 1823.54,3125.35 1934,3235.81 1934,3919 1939.81,3924.81 2010,3924.81 2073.19,3924.81 2080,3918
VBAT_INT on PWR1 "NONET_L-01_P-001" (solid, remove dead copper, pour order 457): 2035,492.81 2035,420.81 2059,396.81 2447,396.81 2465,414.81 2465,523.81 2455,533.81 2076,533.81
AGND on PWR1 "AGND_L04_P486" (solid, pour order 486): 1547.63,1463.97 1519.54,1491.88 1503.96,1491.88 1494.48,1481.94 1477.42,1481.94 1470.52,1491.88 1453.33,1491.88 1422.63,1463.97 1422.63,1454.09 1451.77,1424.94 1464.92,1424.94 1476.93,1436.94 1493.43,1436.94 1505.42,1424.94 1519.13,1424.95 1547.63,1453.45
3V3_VIO on PWR1 "PWR1-3V3_VIO" (solid, remove dead copper, pour order 488): 3068,1829.5 3068,1983.81 3047,2004.81 2974.41,1932.22 2974.41,1925.22 2959,1909.81 2959,1726.07 2968.94,1716.12 3068,1716.12
FTDI_3V3 on PWR1 "PWR1-FTDI_3V3" (solid, remove dead copper, pour order 489): 513.61,4230.71 513.61,4373.88 700.38,4560.65 799.23,4560.65 921.37,4682.8 1392.36,4682.8 1463.07,4612.08 1463.07,4229.61 1448.62,4215.16 1390.16,4215.16 1278.51,4326.8 670.91,4326.8 608.35,4264.24 608.35,4230.71
GND on PWR2 "PWR2-GND" (solid, remove dead copper, pour order 479): -8.55,4956.81 3434.22,4956.81 3434.22,-23.06 -8.55,-23.06
1V2 on PWR2 "PWR1-1V2" (solid, remove dead copper, pour order 63): 2263.79,3637.22 2493.59,3637.22 2534,3596.81 2555.22,3596.81 2561.7,3603.28 2561.7,3621.11 2525.77,3657.04 2099.77,3657.04 2068,3688.81 2068,3802.52 1988.73,3881.79 1988.73,4190.54 2030,4231.81 2232,4231.81 2360.01,4103.81 2533.2,4103.81 2587.63,4049.38 2587.63,3974.97 2603.61,3959 2660.19,3959 2690.93,3989.74 2690.93,4116.74 2698.63,4124.44 2698.63,4271.11 2591.93,4377.81 1894,4377.81 1798,4281.81 1798,3861.81 1902,3757.81 1902,3012.54 1902,2895.32 865.49,1867.23 865.49,1739.71 865.49,1370.62 805.45,1310.59 805.45,961.69 858.97,961.69 911.79,909.77 1084,909.77 1084,1721.81 2068,2705.81 2068,2861.81 2068,3441.43
3V3 on PWR2 "PWR2-3V3" (solid, remove dead copper, pour order 71): 2906.37,1969.34 2917,1958.71 2917,1722.81 2897,1702.81 2833,1702.81 2811,1724.81 2811,1818.27 2726.84,1902.43 2595.78,2033.5 2594,2033.5 2462.2,2165.29 2462.2,2968.01 2532,3037.81 2652,3157.81 2652,3515.81 2615.06,3552.75 2615.06,3591.85 2621.02,3597.81 2646,3597.81 2652,3603.81 2652,3806.61 2803,3957.61 2803,4154.81 2819,4170.81 2859,4170.81 2883,4146.81 2883,3826.81 2779,3722.81 2779,3092.81 2613,2926.81 2613,2262.71 2759.25,2116.45
REGOUT_3V3 on PWR2 "PWR1-REGOUT_3V3" (solid, remove dead copper, pour order 463): 1604.38,1338.97 1633.35,1310 1741,1310 1772.8,1278.2 1772.8,1139 1770.55,1139 1745.52,1113.97 1745.52,932.05 1726.47,913 1497.52,913 1493.87,916.65 1493.68,916.46 1402.33,916.46 1373.06,887.19 1372.41,885.3 1372.41,782.28 2069.21,782.28 2238.93,952 2497.89,952 2922.12,1376.23 2921.64,1445.84 2541.47,1826.01 2431.86,1826.01 2359.06,1898.81 2265,1898.81 2252,1885.81 2252,1848.81 2284,1816.81 2284,1729.63 2142.63,1588.26 1927.43,1588.26 1670.28,1588.26 1670.28,1416.08 1604.38,1350.18
VDDIO_ETH2 on PWR2 "PWR2-VDDIO_ETH2" (solid, remove dead copper, pour order 390): 1000.89,3104.54 1078.25,3104.54 1158.51,3024.28 1595.04,3024.28 1615.02,3044.25 1615.02,3241.71 1525.69,3331.04 1356.86,3331.04 1331.39,3356.51 1331.39,3436.64 1565.74,3436.64 1767.86,3234.52 1767.86,3050.75 1601.33,2884.22 1113.72,2884.22 963,3034.93 963,3066.65
PVIN3V3 on PWR2 "NONET_L-01_P-001" (solid, remove dead copper, pour order 386): 1593.88,1437.96 1556.36,1400.44 1556.8,1359 1556.8,1281.93 1655.43,1183.3 1655.43,1112 1654.99,1111.56 1654.99,1015.76 1644.23,1005 1481.13,1005 1479.13,1003 1414.86,1003 1407.19,1011.33 1346.96,1071.55 1191.21,1071.55 1191.21,1549.89 1394.51,1753.19 1565.3,1753.19 1592.46,1726.03 1593.88,1724.55
AGND on PWR2 "AGND_L05_P073" (solid, pour order 73): 1547.63,1463.97 1519.54,1491.88 1503.96,1491.88 1494.48,1481.94 1477.42,1481.94 1470.52,1491.88 1453.33,1491.88 1422.63,1463.97 1422.63,1454.09 1451.77,1424.94 1464.92,1424.94 1476.93,1436.94 1493.43,1436.94 1505.42,1424.94 1519.13,1424.95 1547.63,1453.45
REGOUT_3V3 on PWR2 "PWR2-REGOUT_3V3" (solid, remove dead copper, pour order 453): 1756.78,3406.72 1837.53,3406.72 1837.53,3336.81 1756.78,3336.81
no net on Top Solder "NONET_L-01_P-001" (solid): 2331.98,4138.07 2232.24,4038.33 2232.24,3687.76 2247.12,3672.88 2525.77,3672.88 2550.79,3647.86 2615.83,3647.86 2635.38,3667.42 2707.42,3667.42 2719,3679 2719,3693 2727.51,3701.51 2727.51,3744.03 2718.59,3752.94 2718.59,3942.49 2702.09,3959 2603.61,3959 2587.63,3974.97 2587.63,4119.54 2569.1,4138.07
no net on Top Solder (solid): 1601.73,4452.2 1689.61,4452.2 1689.61,4570.74 1601.73,4570.74

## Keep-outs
PWR1:
  circle w0: c997.01,2516.33 r16
  circle w0: c997.01,2575.38 r16
  circle w0: c1281.2,2575.38 r16
  circle w0: c2622.78,3578 r20
  circle w0: c2840.2,3889.81 r20
  circle w0: c2821.23,3706 r20
  circle w0: c2552.23,3609.05 r20
PWR2:
  circle w0: c2823.89,3803.87 r16
  circle w0: c2592.55,4179 r16
  circle w0: c2552.55,4202.81 r16
  circle w0: c1990.24,4021.93 r16
  circle w0: c1990.24,4045.51 r16
  circle w0: c1408.92,2090.14 r20
  circle w0: c1408.92,2126.16 r20
  circle w0: c1408.92,2169.91 r20
Keep-Out Layer:
  text ".Layer_Name" at 931.33,-846.68 h60

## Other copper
Top Layer:
  pour cut-out: 1663.15,1593.03 1816.01,1593.03 1816.01,1578.98 1663.14,1578.98
  pour cut-out: 1833.46,1913 1890.33,1856.13 1890.33,1847 1877.03,1847 1832.08,1891.95 1832.08,1892 1831.08,1893
  pour cut-out: 1676.8,1669.19 1676.8,1587.78 1662.75,1587.78 1662.75,1669.2
  pour cut-out: 1870.2,1868.58 1870.2,1806.53 1889.65,1806.53 1890.22,1807.1 1890.22,1848.56
  pour cut-out: 1831.13,1893.23 1833.51,1895.61 1833.51,1913.25 1794.05,1913.25 1794.05,1893.8 1794.62,1893.23
  pour cut-out: 473.41,3677.84 473.41,3464.33 806.94,3464.33 806.94,3677.84
  pour cut-out: 2918.14,1762.04 2939.53,1762.04 2948.71,1752.85 2948.71,1701.18 2920.98,1701.18 2917.44,1704.72
  text ".Layer_Name" at 931.33,-846.68 h60
PWR1:
  text "PWR1" at 950,-848.19 h60
PWR2:
  text "PWR2" at 950,-848.19 h60
GND1:
  text "GND1" at 948.77,-848.19 h60
SIG1:
  text "SIG1" at 948.77,-848.19 h60
SIG2:
  text "SIG2" at 945.99,-848.19 h60
GND2:
  pour cut-out: 2247,3717.81 2260.45,3704.36 2260.45,3700.81 2250,3700.81 2237,3687.81 2237,3614.81 2185,3562.81 2030.2,3562.81 2007,3586.01 2007,3734.81 2040,3767.81 2178,3767.81 2205,3794.81 2210,3794.81 2210,3786.81 2182,3758.81 2043,3758.81 2015,3730.81 2015,3590.41 2034.6,3570.81 2180,3570.81 2228,3618.81 2228,3698.81
  text "GND4" at 950,-848.19 h60
Bottom Layer:
  region net GND: 2673.67,3955.72 2674.18,3955.21 2674.18,3945.18 2672.14,3943.13 2649.16,3943.13 2649.16,3949.43 2652.31,3952.58 2670.53,3952.58
  pour cut-out: 2527.25,3560.81 2627.25,3560.81 2627.25,3504.81 2527.25,3504.81
  pour cut-out: 2795.86,3595.41 2799.47,3591.81 2853,3591.81 2853,3595.41
  pour cut-out: 2300,3411.81 2300,3311.81 2280,3311.81 2280,3411.81
  pour cut-out: 2200,3431.81 2300,3431.81 2300,3411.81 2200,3411.81
  pour cut-out: 2071,3842.81 2071,3771.29 2060,3760.29 2060,3831.81
  pour cut-out: 2000,4071.81 1998,4069.81 1981,4069.81 1981,4150.81 1980,4151.81 2120,4151.81 2120,4141.14 2110.67,4131.81 2000,4131.81
  pour cut-out: 2360,4291.81 2300,4291.81 2288.24,4280.05 2288.24,4250.58 2279.35,4259.47 2279.35,4291.16 2300,4311.81 2360,4311.81
  pour cut-out: 2820,4271.81 2820,4211.81 2799.19,4191 2796.81,4191 2796.81,4251.81 2755.08,4251.81 2754.91,4251.64 2754.91,4266.72 2760,4271.81
  pour cut-out: 2210,3794.81 2210,3786.81 2182,3758.81 2043,3758.81 2015,3730.81 2015,3590.41 2034.6,3570.81 2180,3570.81 2228,3618.81 2228,3698.81 2248,3718.81 2248,3698.81 2237,3687.81 2237,3614.81 2185,3562.81 2030.2,3562.81 2007,3586.01 2007,3734.81 2040,3767.81 2178,3767.81 2205,3794.81
  pour cut-out: 703.54,3523.28 703.54,3450.94 775.36,3451.45 815.95,3410.87 1301.93,3410.87 1301.93,3248.95 1407.96,3248.95 1407.97,3389.02 1561.84,3389.02 1561.84,3585.3 1420.24,3726.9 807.72,3726.9 773.12,3692.3 701.95,3692.27 701.95,3621.13
  pour cut-out: 1494.2,987.83 1514.68,987.82 1514.68,979.57 1513.37,978.26 1497.34,978.26 1494.04,981.56 1494.04,987.62
  pour cut-out: 1165.35,1779.53 1165.35,1952.76 1444.88,1952.76 1468.5,1929.13 1716.54,1929.13 1716.54,1944.88 1728.35,1944.88 1728.35,1917.32 1464.57,1917.32 1444.88,1937.01 1181.1,1937.01 1181.1,1779.53
  pour cut-out: 1254.66,1576.07 1254.66,1611.37 1280.58,1637.29 1299.59,1618.29 1299.59,1576.07
  pour cut-out: 1260.07,1226.95 1253.05,1226.91 1253.05,1325.11 1272.14,1325.11 1291.09,1306.16 1291.09,1299.66 1260.07,1268.52
  pour cut-out: 931.35,1177.66 970.16,1177.66 970.16,1120.05 955.4,1120.05 951.74,1123.71 951.74,1157.27
  pour cut-out: 1836.59,1972.22 1836.33,1957.57 1782.89,1957.57 1781.75,1956.42 1770.41,1967.77 1774.37,1972.22
  pour cut-out: 846.65,1915.64 913.82,1982.81 1186.38,1982.81 1186.38,1952.76 1127.11,1952.76 1116.74,1963.12 924.05,1963.12 859.68,1898.75 859.68,1741.51 898.83,1741.51 899.2,1741.89 899.2,1693.97 892.14,1686.92 886.2,1686.92 876.54,1696.57 876.54,1730.37 846.65,1730.37
  pour cut-out: 1695.11,1485.76 1695.11,1417.4 1695.93,1416.58 1691.12,1411.77 1691.12,1356.4 1771.92,1356.4 1771.92,1408.95
  pour cut-out: 1210.38,1509.77 1256.04,1509.77 1256.04,1387.62 1210.38,1387.62
  text ".Layer_Name" at 931.33,-846.68 h60

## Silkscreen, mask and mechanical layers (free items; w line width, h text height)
Top Overlay:
  circle w3.47: c648.22,4115.71 r10.78
  circle w3.47: c648.22,4115.71 r10.78
  lines w0.87: 557.91,4040.05 653.43,4087.38 ; 653.43,4087.38 551.5,4052.88 653.43,4087.38
  lines w1.73: 647.02,4084.6 634.71,4079.06 647.02,4084.6 ; 647.02,4084.6 635.4,4080.62 647.02,4084.6
  lines w3.47: 634.71,4079.58 553.75,4052.01 634.71,4079.58 ; 634.71,4079.58 557.05,4041.79 634.71,4079.58
  lines w6.93: 566.41,4049.24 550.63,4043.52 566.41,4049.24 ; 566.41,4049.24 559.47,4051.67 566.41,4049.24 ; 389.59,4116.85 399.13,4121.7 389.59,4116.85 ; 556.7,4047.68 607.32,4068.13 556.7,4047.68
  lines w15.6: 324.07,4058.25 309.51,4042.13 324.07,4058.25 ; 324.07,4058.25 333.6,4067.96 ; 324.07,4058.25 333.6,4067.96 ; 333.6,4067.96 342.27,4076.28 ; 333.6,4067.96 342.27,4076.28 ; 342.27,4076.28 346.78,4080.62 ; 342.27,4076.28 346.78,4080.62 ; 346.78,4080.62 357.18,4088.94 ; 346.78,4080.62 357.18,4088.94 ; 357.18,4088.94 366.89,4096.91 ; 357.18,4088.94 366.89,4096.91 ; 366.89,4096.91 370.7,4099.51 ; 366.89,4096.91 370.7,4099.51 ; 370.7,4099.51 375.21,4102.28 ; 370.7,4099.51 375.21,4102.28 ; 375.21,4102.28 382.31,4106.79 375.21,4102.28 ; 391.33,4113.03 373.82,4102.11 391.33,4113.03 ; 391.33,4113.03 374.51,4102.28 391.33,4113.03 ; 403.81,4059.81 ccw(c413.38,4052.52) 420.97,4043.17 ; 403.81,4059.81 ccw(c413.38,4052.52) 420.97,4043.17 ; 403.81,4059.81 437.61,4104.19 ; 403.81,4059.81 437.61,4104.19 ; 411.26,4122.74 399.82,4117.19 411.26,4122.74 ; 411.26,4122.74 420.1,4126.38 ; 411.26,4122.74 420.1,4126.38 ; 420.1,4126.38 cw(c427.93,4109.71) 437.09,4125.69 ; 420.1,4126.38 cw(c427.93,4109.71) 437.09,4125.69 ; 420.97,4043.17 cw(c670.44,3608.43) 523.77,4087.72 ; 420.97,4043.17 cw(c670.44,3608.43) 523.77,4087.72 ; 437.09,4125.69 cw(c433.28,4119.03) 440.73,4120.83 ; 437.09,4125.69 cw(c433.28,4119.03) 440.73,4120.83 ; 437.61,4104.19 ccw(c420.65,4115.98) 440.73,4120.83 ; 437.61,4104.19 ccw(c420.65,4115.98) 440.73,4120.83 ; 523.77,4087.72 cw(c525.48,4075.2) 537.81,4078.02 ; 523.77,4087.72 cw(c525.48,4075.2) 537.81,4078.02 ; 537.81,4078.02 cw(c488.94,4066.84) 538.33,4058.25 ; 537.81,4078.02 cw(c488.94,4066.84) 538.33,4058.25 ; 538.33,4058.25 ccw(c549.61,4056.29) 553.23,4045.43 cw(c549.61,4056.29) 538.33,4058.25 ; 379.54,4104.88 385.95,4109.22 379.54,4104.88 ; 382.83,4107.66 395.14,4114.42 382.83,4107.66
  text "VPP_1P7" at 486.81,4734.4 h40
  text "GND" at 677.97,4536.87 h40
  text "FTDI_NSUSP" at 1216.64,4421.76 h35 r90
  text "WRMRST" at 1288,4253.81 h35
  text "FTDI_USB" at 304.63,4247.11 h60 r90
  text "R" at 644.23,4111.2 h10.4
  text "R" at 644.23,4111.2 h10.4
  text "MISTRAL" at 301.36,3958.75 h80
  text "OSC_CLKTOP" at 843.76,3456.81 h40
  text "ETH_LED" at 284.18,3199.66 h50
  text "RJ45_VCC" at 727.06,2295.63 h40
  text "ETH_CLKOUT" at 1242.97,2233.92 h40
  text "ETH_LED" at 187.13,2163.9 h40
  text "MSS_GPIO2" at 3009.2,2015.81 h40 r90
  text "TRIG_GPIO" at 193.17,1954.21 h40
  text "AWR2E44PEVM" at 1956.55,1914 h60
  text "'.PRJ_Number'" at 2081.95,1817 h60
  text "GND" at 3115.39,1769.98 h40
  text "REV. A" at 2233.6,1706.91 h60
  text "NRST" at 338.25,1687.43 h40 r90
  text "3V3" at 2885,1661.81 h40 r90
  text "1V0" at 832.53,1648.95 h40
  text "JTAG_MUX" at 2637.84,1565.9 h35
  text "XDS" at 2773.62,1489.82 h35
  text "REGOUT_3V3" at 3008,1489.81 h40 r90
  text "NRST" at 172.83,1476.13 h40
  text "XDS_USB" at 3100.17,1394.93 h50 r90
  text "DEBUG_CONN" at 324.77,1369.35 h60
  text "CAUTION  / HOT" at 1215.74,1369.28 h25
  text "MIPI" at 2773.49,1344.72 h35
  text "SURFACE" at 1270.9,1328.34 h25
  text "NERR_OUT" at 1034,1277.81 h40
  text "MOSI" at 3210.97,1244.1 h40
  text "CS0" at 2692.55,1238.86 h40
  text "For evaluation only; not FCC approved for resale." at 1773,1216.81 h60
  text "CLK" at 2707.67,1133.91 h40
  text "MISO" at 2694.08,956.16 h40
  text "WAKE" at 3205.88,954.09 h40
  text "PMIC_DBG" at 2868.94,898.76 h60
  text "GND" at 3129.84,707.28 h40
  text "GND" at 1386.18,667.7 h40
  text "CANB_WAKE" at 66.16,651.03 h40 r90
  text "CANA_H" at 969.21,376.44 h40 r90
  text "CANA_L" at 1294.13,376.36 h40 r90
  text "CANB_L" at 748.43,374.82 h40 r90
  text "GND" at 1129.19,374.75 h40 r90
  text "GND" at 604.99,373.35 h40 r90
  text "VBAT" at 2156.2,265.46 h40
  text "CANB_H" at 357.62,167.57 h40 r90
  text "SOP0" at 2071.79,78.91 h40
  text "SOP1" at 1814.76,37.39 h40
  text "SOP2" at 1573.64,35.63 h40
  text ".Layer_Name" at 931.33,-846.68 h60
